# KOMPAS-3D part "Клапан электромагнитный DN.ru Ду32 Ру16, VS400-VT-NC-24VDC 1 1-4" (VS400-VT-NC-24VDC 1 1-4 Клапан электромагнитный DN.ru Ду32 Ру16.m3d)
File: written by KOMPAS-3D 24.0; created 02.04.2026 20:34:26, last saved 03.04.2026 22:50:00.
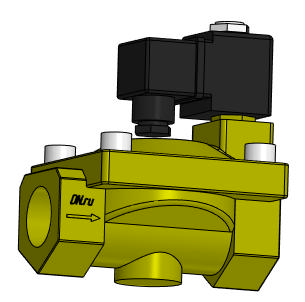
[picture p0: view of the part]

Document properties: Автор: artio; Полное имя файла: C:\Users\artio\OneDrive\Рабочий стол\Клапан электромагнитный DN.ru\VS400-VT-NC\VS400-VT-NC-24VDC 1 1-4 Клапан электромагнитный DN.ru Ду32 Ру16.m3d

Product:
- Body: Тело 1  | qty 1
    Масса: 4.144257
- Part/product: Клапан электромагнитный DN.ru Ду32 Ру16  | designation VS400-VT-NC-24VDC 1 1-4
    Масса: 2.569
    Раздел спецификации: Прочие изделия
    Примечание: D130-04736
    additional columns: ef56311e-7521-43dc-8291-0e6108b3d81d; VS400-ET-NC-220VAC 1 1-4; artio; c; Шероховатость не задана; Да

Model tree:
1. Операция без истории:1

Expressions: VS400-VT-NC-24VDC 1 1-4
